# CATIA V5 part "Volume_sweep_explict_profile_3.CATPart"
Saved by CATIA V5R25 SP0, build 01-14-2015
Part number: Part1
Bounding box of the stored display mesh (mm): x -10 to 10, y -11.926 to 23.216, z 0 to 127.487
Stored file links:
  E:\cadcim\GSD_cat_v5-6r2014\Part_files\Volume_sweep_explict_profile_3.CATPart
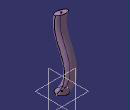
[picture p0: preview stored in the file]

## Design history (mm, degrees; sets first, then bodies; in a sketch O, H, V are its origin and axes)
Set1
  Sketch1 on xy-plane, origin (0, 0, 0), H (1, 0, 0), V (0, 1, 0)
    circle A1 centre (0, 0) radius 10
    radius A1 = 10
  Sketch2 on yz-plane, origin (0, 0, 0), H (0, 1, 0), V (0, 0, 1)
    spline S1 through (0, 0) (11.9407, 56.843) (-3.4307, 102.6672) (-1.4005, 123.8391)
    point P1 (0, 0)
    coincidence: P1 O
  Sweep1: type Unspec, Profile Sketch1, Guide Sketch2, AngleRef 0, PullingDir zx-plane
Body1 (main body)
